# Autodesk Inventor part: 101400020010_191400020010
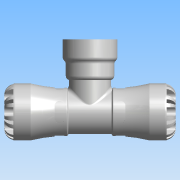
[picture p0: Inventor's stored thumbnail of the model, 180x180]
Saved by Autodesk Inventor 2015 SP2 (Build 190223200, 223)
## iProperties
Created: 2016-12
Part Number: 101400020010_191400020010
Material: PVC-Piping
Description: PLASSON TEE WITH THREADED FEMALE OFFTAKE 20X1" SERIES 1
Document SubType Name: Modeling
Designer: KIM
Mass: 664.223 g
Surface Area: 733.008 cm^2
Volume: 474.445 cm^3
Density: 1.4 g/cm^3
Appearance: Smooth - White
Author: KIM
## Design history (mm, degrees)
derived "1014.ipt"
feature "Solid1::1014.ipt"
tag "TaggingFeature1"
body "Solid1"
other parameters: "d1" = 18.9, "d3" = 25, "d4" = 41, "d8" = 34.85, "d13" = 6.4, "d14" = 6.4, "d15" = 0, "d17" = 360 deg, "d19" = 8 deg, "d20" = 0.4, "d21" = 0.4, "d22" = 8 deg, "d24" = 0, "d26" = 360 deg, "d33" = 4.1, "d43" = 31.98, "d51" = 0.41, "d54" = 7, "d55" = 4.4, "d57" = 12.544, "d58" = 0, "d74" = 0, "d77" = 1.66667, "d78" = 45, "d79" = 31.98, "d80" = 123, "d82" = 0.4, "d115" = 360 deg, "d139" = 6.4, "d140" = 0, "d142" = 360 deg, "d207" = 90 deg, "d228" = 5.95, "d247" = 0.82, "d248" = 2.7, "d266" = 0, "d268" = 30.291, "d270" = 4.54365, "d271" = 7, "d274" = 2.27183, "d275" = 52, "d276" = 3.0291, "d277" = 3.0291, "d278" = 3.0291, "d279" = 3.0291, "d281" = 0, "d282" = 21, "E_" = 41, "l_" = 45, "A_" = 52, "H_" = 123, "Rp_" = 30.291, "l_2" = 21, "d9" = 8, "d11" = 41, "d12" = 25
